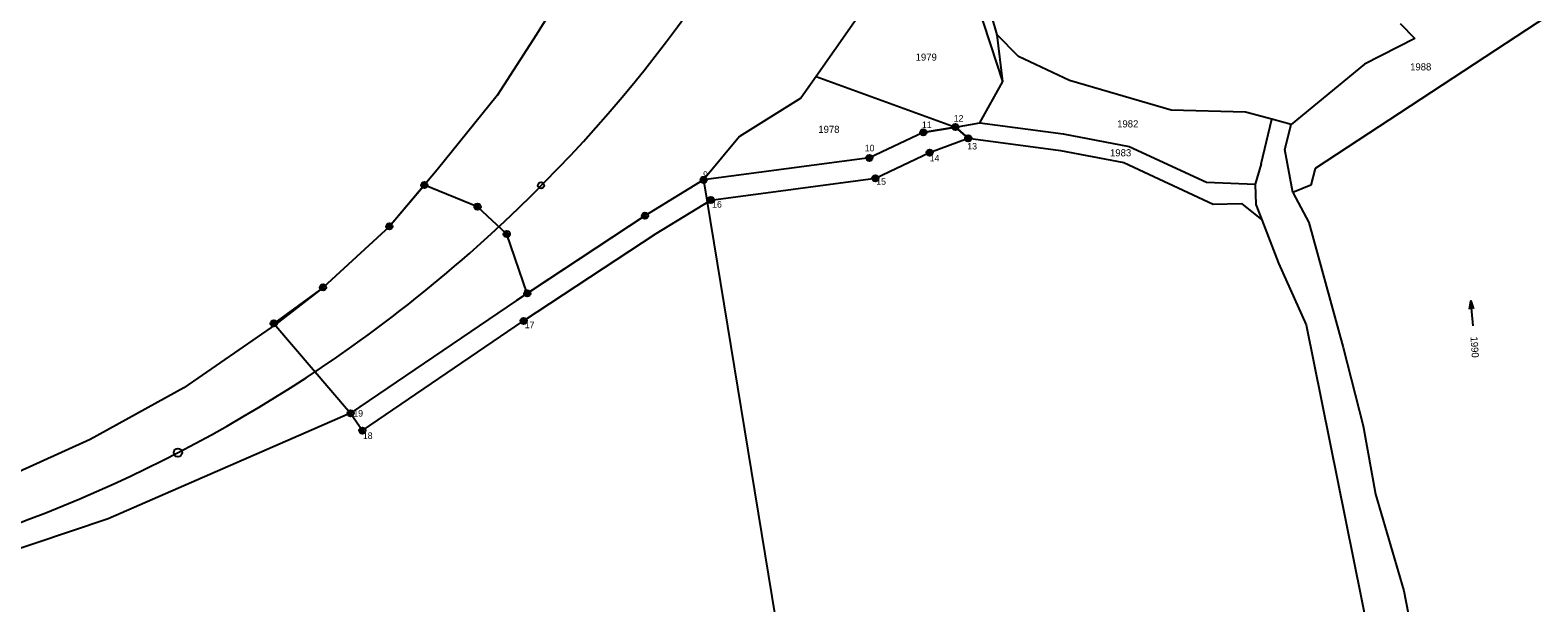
# Model space of a CAD drawing. Extents: x -802857 to -799647, y -1020285 to -1015884.
# Drawn here: x -801308.3 to -800948.7, y -1017248.9 to -1017112.3 of the extents above; entities that cross this region are included whole.
import ezdxf

# ---------------------------------------------------------------- set-up
doc = ezdxf.new("R2010")
doc.units = 0
for name, color, linetype in [('05a - kolej - svršek', 7, 'Continuous'), ('body', 7, 'Continuous'), ('cisla', 7, 'Continuous'), ('Default', 7, 'Continuous'), ('KN_HRANICE', 7, 'Continuous'), ('KN_KULTURY', 7, 'Continuous'), ('KN_PARCELY', 7, 'Continuous'), ('obvod_stavby', 7, 'Continuous'), ('Svršek_hkm_100', 7, 'Continuous'), ('Železniční svršek', 7, 'Continuous')]:
    doc.layers.add(name, color=color, linetype=linetype)

# ---------------------------------------------------------------- blocks, each defined once
blk = doc.blocks.new('802')
at = {"layer": 'Default'}
blk.add_line((-3, 0), (3, 0), dxfattribs=at)
blk.add_lwpolyline([(1, 0.5), (3, 0), (1, -0.5)], dxfattribs=at)
blk = doc.blocks.new('C513')
at = {"layer": 'Default'}
blk.add_circle((0, 0), 0.75, dxfattribs=at)

msp = doc.modelspace()

# ---------------------------------------------------------------- linework, layer by layer
at = {"layer": 'body'}
for p, q in [((-801095.3, -1017136.72), (-801095.3, -1017136.72)), ((-801087.64, -1017135.44), (-801087.64, -1017135.44)), ((-801084.58, -1017138.12), (-801084.58, -1017138.12)), ((-801093.79, -1017141.54), (-801093.79, -1017141.54)), ((-801108.14, -1017142.81), (-801108.14, -1017142.81)), ((-801147.67, -1017148.04), (-801147.67, -1017148.04)), ((-801106.71, -1017147.66), (-801106.71, -1017147.66)), ((-801214.28, -1017149.29), (-801214.28, -1017149.29)), ((-801201.6, -1017154.44), (-801201.6, -1017154.44)), ((-801145.96, -1017152.86), (-801145.96, -1017152.86)), ((-801222.62, -1017159.13), (-801222.62, -1017159.13)), ((-801161.67, -1017156.6), (-801161.67, -1017156.6)), ((-801194.62, -1017160.96), (-801194.62, -1017160.96)), ((-801238.45, -1017173.69), (-801238.45, -1017173.69)), ((-801189.73, -1017175.11), (-801189.73, -1017175.11)), ((-801250.19, -1017182.28), (-801250.19, -1017182.28)), ((-801190.6, -1017181.7), (-801190.6, -1017181.7)), ((-801231.87, -1017203.72), (-801231.87, -1017203.72)), ((-801229.06, -1017207.85), (-801229.06, -1017207.85))]:
    msp.add_line(p, q, dxfattribs=at)
for centre, radius in [((-801095.3, -1017136.72), 0.75), ((-801095.3, -1017136.72), 0.35), ((-801087.64, -1017135.44), 0.75), ((-801087.64, -1017135.44), 0.35), ((-801084.58, -1017138.12), 0.75), ((-801084.58, -1017138.12), 0.35), ((-801093.79, -1017141.54), 0.75), ((-801093.79, -1017141.54), 0.35), ((-801108.14, -1017142.81), 0.75), ((-801108.14, -1017142.81), 0.35), ((-801214.28, -1017149.29), 0.75), ((-801214.28, -1017149.29), 0.35), ((-801147.67, -1017148.04), 0.75), ((-801147.67, -1017148.04), 0.35), ((-801106.71, -1017147.66), 0.75), ((-801106.71, -1017147.66), 0.35), ((-801145.96, -1017152.86), 0.75), ((-801145.96, -1017152.86), 0.35), ((-801201.6, -1017154.44), 0.75), ((-801201.6, -1017154.44), 0.35), ((-801161.67, -1017156.6), 0.75), ((-801222.62, -1017159.13), 0.75), ((-801222.62, -1017159.13), 0.35), ((-801161.67, -1017156.6), 0.35), ((-801194.62, -1017160.96), 0.75), ((-801194.62, -1017160.96), 0.35), ((-801238.45, -1017173.69), 0.75), ((-801238.45, -1017173.69), 0.35), ((-801189.73, -1017175.11), 0.75), ((-801189.73, -1017175.11), 0.35), ((-801190.6, -1017181.7), 0.75), ((-801190.6, -1017181.7), 0.35), ((-801250.19, -1017182.28), 0.75), ((-801250.19, -1017182.28), 0.35), ((-801231.87, -1017203.72), 0.75), ((-801231.87, -1017203.72), 0.35), ((-801229.06, -1017207.85), 0.75), ((-801229.06, -1017207.85), 0.35)]:
    msp.add_circle(centre, radius, dxfattribs=at)
at = {"layer": 'KN_HRANICE'}
for p, q in [((-801179.48, -1017100.28), (-801187.5, -1017113.35)), ((-801107.38, -1017104.16), (-801120.85, -1017123.38)), ((-800941.26, -1017105.59), (-801001.86, -1017145.37)), ((-801077.69, -1017113.44), (-801079.03, -1017108.8)), ((-801079.17, -1017115.86), (-801081.08, -1017110)), ((-800981.55, -1017110.76), (-800978.03, -1017114.36)), ((-801187.5, -1017113.35), (-801196.91, -1017127.94)), ((-801076.29, -1017124.55), (-801079.17, -1017115.86)), ((-801076.29, -1017124.55), (-801077.69, -1017113.44)), ((-801072.61, -1017118.61), (-801077.69, -1017113.44)), ((-800978.03, -1017114.36), (-800990.08, -1017120.48)), ((-801060.39, -1017124.37), (-801072.61, -1017118.61)), ((-801120.85, -1017123.38), (-801124.46, -1017128.53)), ((-801120.85, -1017123.38), (-801087.64, -1017135.44)), ((-800990.08, -1017120.48), (-801007.59, -1017134.85)), ((-801081.77, -1017134.46), (-801076.29, -1017124.55)), ((-801036.16, -1017131.43), (-801060.39, -1017124.37)), ((-801196.91, -1017127.94), (-801211.22, -1017145.68)), ((-801124.46, -1017128.53), (-801139.16, -1017137.71)), ((-801087.64, -1017135.44), (-801081.77, -1017134.46)), ((-801081.77, -1017134.46), (-801061.94, -1017137.05)), ((-801018.45, -1017131.86), (-801036.16, -1017131.43)), ((-801012.13, -1017133.6), (-801018.45, -1017131.86)), ((-801014.73, -1017144.22), (-801012.13, -1017133.6)), ((-801007.59, -1017134.85), (-801012.13, -1017133.6)), ((-801139.16, -1017137.71), (-801147.67, -1017148.04)), ((-801095.3, -1017136.72), (-801108.14, -1017142.81)), ((-801095.3, -1017136.72), (-801087.64, -1017135.44)), ((-801087.64, -1017135.44), (-801084.58, -1017138.12)), ((-801084.58, -1017138.12), (-801062.58, -1017141)), ((-801061.94, -1017137.05), (-801046.19, -1017140.07)), ((-801009.05, -1017140.81), (-801007.59, -1017134.85)), ((-801062.58, -1017141), (-801047.43, -1017143.9)), ((-801046.19, -1017140.07), (-801027.73, -1017148.59)), ((-801007.17, -1017151.05), (-801009.05, -1017140.81)), ((-801108.14, -1017142.81), (-801147.67, -1017148.04)), ((-801047.43, -1017143.9), (-801026.14, -1017153.86)), ((-801014.73, -1017144.22), (-801016.11, -1017149.08)), ((-801001.86, -1017145.37), (-801002.87, -1017149.33)), ((-801211.22, -1017145.68), (-801222.62, -1017159.13)), ((-801147.67, -1017148.04), (-801161.67, -1017156.6)), ((-801147.67, -1017148.04), (-801120.7, -1017312.51)), ((-801027.73, -1017148.59), (-801016.11, -1017149.08)), ((-801016.11, -1017149.08), (-801015.97, -1017153.92)), ((-801002.87, -1017149.33), (-801007.17, -1017151.05)), ((-801007.17, -1017151.05), (-801003.34, -1017158.2)), ((-801026.14, -1017153.86), (-801019.43, -1017153.68)), ((-801019.43, -1017153.68), (-801014.57, -1017157.55)), ((-801015.97, -1017153.92), (-801014.57, -1017157.55)), ((-801222.62, -1017159.13), (-801238.45, -1017173.69)), ((-801161.67, -1017156.6), (-801192.33, -1017176.83)), ((-801014.57, -1017157.55), (-801010.59, -1017167.92)), ((-801003.34, -1017158.2), (-800995.15, -1017188.06)), ((-801010.59, -1017167.92), (-801003.97, -1017182.58)), ((-801238.45, -1017173.69), (-801249.76, -1017182.55)), ((-801192.33, -1017176.83), (-801231.87, -1017203.72)), ((-801249.76, -1017182.55), (-801271.65, -1017197.67)), ((-801003.97, -1017182.58), (-800982.5, -1017289.15)), ((-800995.15, -1017188.06), (-800990.37, -1017206.68)), ((-801271.65, -1017197.67), (-801294.01, -1017209.98)), ((-801231.87, -1017203.72), (-801289.7, -1017228.88)), ((-801294.01, -1017209.98), (-801312.74, -1017218.5)), ((-800990.37, -1017206.68), (-800987.47, -1017223.03)), ((-800987.47, -1017223.03), (-800980.69, -1017246.06)), ((-801289.7, -1017228.88), (-801318.92, -1017238.69)), ((-800980.69, -1017246.06), (-800976.35, -1017268.19))]:
    msp.add_line(p, q, dxfattribs=at)
at = {"layer": 'obvod_stavby'}
msp.add_lwpolyline([(-801087.64, -1017135.44), (-801095.3, -1017136.72), (-801108.14, -1017142.81), (-801147.67, -1017148.04), (-801161.67, -1017156.6), (-801189.73, -1017175.11), (-801194.62, -1017160.96), (-801201.6, -1017154.44), (-801214.28, -1017149.29), (-801222.62, -1017159.13), (-801238.45, -1017173.69), (-801250.19, -1017182.28), (-801231.87, -1017203.72), (-801229.06, -1017207.85), (-801190.6, -1017181.7), (-801158.99, -1017160.82), (-801145.96, -1017152.86), (-801106.71, -1017147.66), (-801093.79, -1017141.54), (-801084.58, -1017138.12), (-801087.64, -1017135.44)], dxfattribs=at)
at = {"layer": 'Svršek_hkm_100'}
msp.add_circle((-801273.05, -1017213.08), 1, dxfattribs=at)
at = {"layer": 'Železniční svršek'}
for start, end in [(311.7457, 358.6036), (305.4132, 311.7457), (259.1164, 305.4132)]:
    msp.add_arc((-801431.93, -1016905.94), 345.8, start, end, dxfattribs=at)

# ---------------------------------------------------------------- block references
at = {"layer": '05a - kolej - svršek', "rotation": -134.7448899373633}
msp.add_blockref('C513', (-801186.44, -1017149.36), dxfattribs=at)
at = {"layer": 'KN_KULTURY', "rotation": 95.512064}
msp.add_blockref('802', (-800964.44, -1017179.86), dxfattribs=at)

# ---------------------------------------------------------------- texts
at = {"layer": 'cisla'}
for s, p in [(' 11', (-801096.19, -1017135.67)), (' 12', (-801088.6, -1017134.14)), (' 10', (-801109.82, -1017141.23)), (' 13', (-801085.37, -1017140.79)), (' 14', (-801094.34, -1017143.65)), ('  4', (-801216.35, -1017150.07)), ('  9', (-801148.97, -1017147.56)), (' 15', (-801107.08, -1017149.21)), ('  5', (-801203.67, -1017155.22)), ('  8', (-801163.74, -1017157.38)), (' 16', (-801146.22, -1017154.66)), ('  3', (-801224.69, -1017159.91)), ('  6', (-801196.69, -1017161.74)), ('  2', (-801240.52, -1017174.47)), ('  7', (-801191.8, -1017175.89)), ('  1', (-801252, -1017183.06)), (' 17', (-801190.91, -1017183.42)), (' 19', (-801231.79, -1017204.5)), (' 18', (-801229.52, -1017209.84))]:
    msp.add_text(s, height=1.552, dxfattribs=at).set_placement(p)
at = {"layer": 'KN_PARCELY'}
for s, p in [('1979', (-801097.12, -1017119.62)), ('1988', (-800979.19, -1017121.94)), ('1982', (-801049.06, -1017135.54)), ('1978', (-801120.33, -1017136.85)), ('1983', (-801050.76, -1017142.43))]:
    msp.add_text(s, height=1.7, dxfattribs=at).set_placement(p)
msp.add_text('1990', height=1.7, rotation=273.759, dxfattribs=at).set_placement((-800964.8, -1017185.47))

doc.saveas('drawing.dxf')
